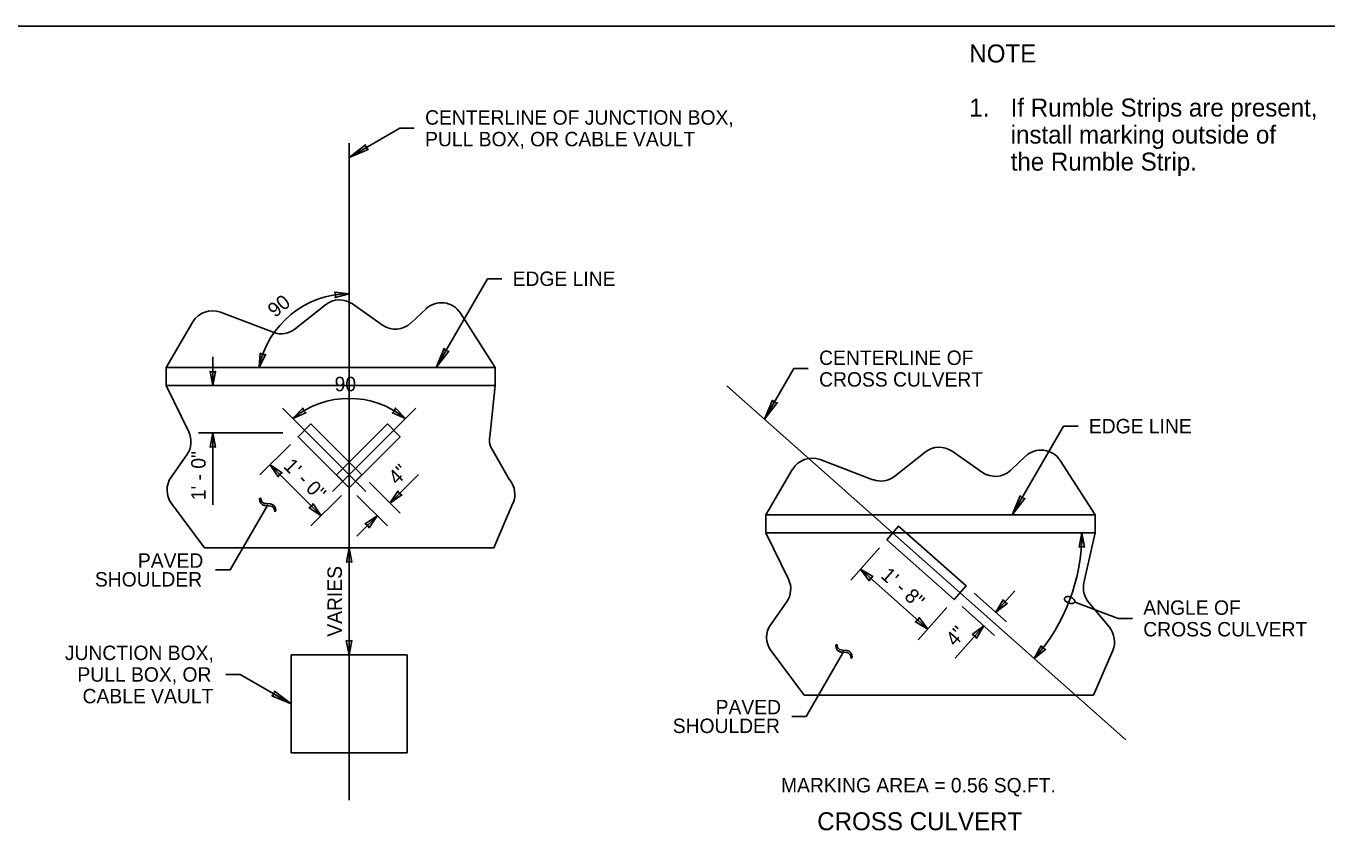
# Model space of a CAD drawing. Extents: x 99862 to 104211, y 98939 to 105076.
# Drawn here: x 101694 to 103137, y 101180 to 102076 of the extents above; entities that cross this region are included whole.
import ezdxf

# ---------------------------------------------------------------- set-up
doc = ezdxf.new("R2010")
doc.units = 0
for name, color, linetype in [('Level 1', 7, 'Continuous'), ('Level 15', 7, 'Continuous'), ('Level 17', 7, 'Continuous'), ('Level 20', 7, 'Continuous'), ('Level 5', 7, 'Continuous'), ('Level 50', 7, 'Continuous'), ('Level 8', 7, 'Continuous')]:
    doc.layers.add(name, color=color, linetype=linetype)

msp = doc.modelspace()

# ---------------------------------------------------------------- linework, layer by layer
at = {"layer": 'Level 1'}
msp.add_lwpolyline([(99862, 99999.5), (103151, 99999.5), (103151, 102075.5), (99862, 102075.5)], close=True, dxfattribs=at)
at = {"layer": 'Level 15'}
for p, q in [((102052.3, 101929.5), (102108.6, 101962)), ((102108.6, 101962), (102124.6, 101962)), ((102052.3, 101216.3), (102052.3, 101945.5)), ((102148.8, 101696.4), (102205.7, 101795)), ((102205.7, 101795), (102221.7, 101795)), ((101901.1, 101676.4), (101901.1, 101708.4)), ((102513.2, 101639), (102545.7, 101695.3)), ((102545.7, 101695.3), (102561.7, 101695.3)), ((102914.1, 101283.3), (102471.3, 101676.1)), ((102070.7, 101558.9), (101978.4, 101651.2)), ((102126.3, 101651.2), (102033.9, 101558.9)), ((102788, 101532.9), (102844.9, 101631.4)), ((102844.9, 101631.4), (102860.9, 101631.4)), ((101978.8, 101623.9), (101885.1, 101623.9)), ((101901.1, 101623.9), (101901.1, 101543.9)), ((101987.3, 101611.2), (101953.3, 101577.3)), ((101964.6, 101588.6), (102021.2, 101532)), ((102097.6, 101546.1), (102129.2, 101577.8)), ((102074.9, 101568.8), (102108.9, 101534.8)), ((101962, 101544.2), (101920.2, 101471.8)), ((101954.1, 101552), (101953, 101550.2)), ((101953, 101550.2), (101953.4, 101548.1)), ((101953.4, 101548.1), (101954, 101546.4)), ((101954, 101546.4), (101955, 101545.1)), ((101955.1, 101548.5), (101954.1, 101552)), ((101955, 101545.1), (101956.3, 101544.1)), ((101955.9, 101547.1), (101955.1, 101548.5)), ((101957, 101546.2), (101955.9, 101547.1)), ((101956.3, 101544.1), (101958.6, 101543.2)), ((101958.4, 101545.6), (101957, 101546.2)), ((101960.8, 101545.4), (101958.4, 101545.6)), ((101965.2, 101545.1), (101960.8, 101545.4)), ((101967.8, 101544.1), (101965.2, 101545.1)), ((101969.2, 101543.1), (101967.8, 101544.1)), ((102043.8, 101554.6), (102009.9, 101520.7)), ((102060.8, 101554.6), (102094.7, 101520.7)), ((101958.6, 101543.2), (101962.7, 101543)), ((101962.7, 101543), (101965.2, 101542.7)), ((101965.2, 101542.7), (101967, 101542.1)), ((101967, 101542.1), (101968.1, 101541.3)), ((101968.1, 101541.3), (101968.9, 101540.2)), ((101968.9, 101540.2), (101969.5, 101538.6)), ((101970.2, 101541.7), (101969.2, 101543.1)), ((101969.5, 101538.6), (101970, 101536.2)), ((101970, 101536.2), (101971.1, 101538)), ((101970.8, 101540), (101970.2, 101541.7)), ((101971.1, 101538), (101970.8, 101540)), ((102083.4, 101532), (102060.8, 101509.4)), ((102052.4, 101496.3), (102052.3, 101377.6)), ((102640.7, 101496.4), (102608.8, 101460.5)), ((101904.2, 101471.8), (101920.2, 101471.8)), ((102619.5, 101472.5), (102694.3, 101406.1)), ((102745.7, 101446), (102781.6, 101414.2)), ((102769.7, 101424.8), (102790.9, 101448.8)), ((102715.5, 101430.1), (102683.7, 101394.2)), ((102732.4, 101431.1), (102768.4, 101399.2)), ((102856.6, 101436.5), (102905.3, 101418)), ((102905.3, 101418), (102921.3, 101418)), ((102756.4, 101409.9), (102724.5, 101373.9)), ((102593.2, 101389.4), (102592.2, 101387.6)), ((102592.2, 101387.6), (102592.5, 101385.5)), ((102592.5, 101385.5), (102593.2, 101383.8)), ((102594.2, 101385.9), (102593.2, 101389.4)), ((102595.1, 101384.5), (102594.2, 101385.9)), ((102601.2, 101381.6), (102559.4, 101309.2)), ((102593.2, 101383.8), (102594.1, 101382.5)), ((102594.1, 101382.5), (102595.5, 101381.5)), ((102596.2, 101383.6), (102595.1, 101384.5)), ((102595.5, 101381.5), (102597.8, 101380.6)), ((102597.6, 101383), (102596.2, 101383.6)), ((102600, 101382.8), (102597.6, 101383)), ((102597.8, 101380.6), (102601.8, 101380.4)), ((102604.4, 101382.5), (102600, 101382.8)), ((102601.8, 101380.4), (102604.4, 101380.2)), ((102606.9, 101381.5), (102604.4, 101382.5)), ((102604.4, 101380.2), (102606.2, 101379.5)), ((102606.2, 101379.5), (102607.2, 101378.7)), ((102608.3, 101380.5), (102606.9, 101381.5)), ((102607.2, 101378.7), (102608, 101377.6)), ((102608, 101377.6), (102608.7, 101376)), ((102609.4, 101379.1), (102608.3, 101380.5)), ((102608.7, 101376), (102609.2, 101373.6)), ((102609.2, 101373.6), (102610.2, 101375.4)), ((102610, 101377.4), (102609.4, 101379.1)), ((102610.2, 101375.4), (102610, 101377.4)), ((101915.6, 101355.8), (101931.6, 101355.8)), ((101987.9, 101323.3), (101931.6, 101355.8)), ((102543.4, 101309.2), (102559.4, 101309.2))]:
    msp.add_line(p, q, dxfattribs=at)
for points in [[(102052.3, 101929.5), (102073.6, 101938.3), (102071.2, 101940.4), (102070.6, 101943.5)], [(102052.3, 101778.3), (102036.9, 101774.1), (102037.4, 101777.2), (102036.4, 101780.2)], [(102148.8, 101696.4), (102162.8, 101714.7), (102159.7, 101715.3), (102157.7, 101717.7)], [(101952.4, 101696.4), (101953.7, 101712.4), (101956.4, 101710.9), (101959.6, 101710.8)], [(101901.1, 101676.4), (101898, 101692.2), (101901.1, 101691.4), (101904.2, 101692.2)], [(102513.2, 101639), (102527.2, 101657.3), (102524, 101657.8), (102522, 101660.2)], [(101989.7, 101639.9), (102004.4, 101646.3), (102002, 101648.5), (102000.8, 101651.4)], [(102114.9, 101639.9), (102100.3, 101646.3), (102102.6, 101648.5), (102103.8, 101651.4)], [(101901.1, 101623.9), (101898, 101608.2), (101901.1, 101608.9), (101904.2, 101608.2)], [(101964.6, 101588.6), (101973.6, 101575.3), (101975.2, 101578), (101977.9, 101579.6)], [(102097.6, 101546.1), (102106.5, 101559.4), (102108.2, 101556.8), (102110.9, 101555.1)], [(102021.2, 101532), (102012.3, 101545.3), (102010.6, 101542.6), (102007.9, 101540.9)], [(102788, 101532.9), (102802, 101551.2), (102798.9, 101551.7), (102796.8, 101554.2)], [(102083.4, 101532), (102070.1, 101523.1), (102072.8, 101521.4), (102074.5, 101518.7)], [(102865.3, 101512.9), (102862, 101497.2), (102865.1, 101497.9), (102868.2, 101497.1)], [(102052.4, 101496.3), (102049.3, 101480.6), (102052.4, 101481.3), (102055.4, 101480.6)], [(102619.5, 101472.5), (102629.2, 101459.8), (102630.7, 101462.5), (102633.3, 101464.4)], [(102769.7, 101424.8), (102777.8, 101438.6), (102779.6, 101436), (102782.4, 101434.5)], [(102694.3, 101406.1), (102684.6, 101418.9), (102683.1, 101416.1), (102680.5, 101414.3)], [(102756.4, 101409.9), (102743.6, 101400.1), (102746.4, 101398.6), (102748.3, 101396)], [(102052.3, 101377.6), (102049.2, 101393.4), (102052.3, 101392.6), (102055.4, 101393.4)], [(102812.4, 101373.5), (102824.9, 101383.5), (102822.1, 101385), (102820.2, 101387.5)], [(101987.9, 101323.3), (101966.7, 101332.1), (101969.1, 101334.1), (101969.7, 101337.3)]]:
    msp.add_lwpolyline(points, close=True, dxfattribs=at)
for centre, radius, start, end in [((102052.3, 101676.4), 101.9, 90, 168.6784), ((102052.3, 101563.1), 99.1, 50.7921, 129.2072), ((102655.3, 101512.9), 210, 318.4255, 0)]:
    msp.add_arc(centre, radius, start, end, dxfattribs=at)
msp.add_ellipse((102851.6, 101438.4), major_axis=(5.61, -2.13), ratio=0.57735, dxfattribs=at)
at = {"layer": 'Level 17'}
for p, q in [((102214.5, 101696.4), (101849.2, 101696.4)), ((102214.5, 101676.4), (101849.2, 101676.4)), ((102514.5, 101532.9), (102879.8, 101532.9)), ((102655.3, 101512.9), (102514.5, 101512.9)), ((102879.8, 101512.9), (102670.4, 101512.9))]:
    msp.add_line(p, q, dxfattribs=at)
for points in [[(102052.3, 101591.4), (102094.7, 101633.8), (102108.9, 101619.7), (102052.3, 101563.1), (101995.7, 101619.7), (102009.9, 101633.8)], [(102648.7, 101505.4), (102723.5, 101439), (102736.7, 101454), (102661.9, 101520.4)]]:
    msp.add_lwpolyline(points, close=True, dxfattribs=at)
at = {"layer": 'Level 5'}
for p, q in [((102661.9, 101520.4), (102648.7, 101505.4)), ((102736.7, 101454), (102661.9, 101520.4)), ((102648.7, 101505.4), (102723.5, 101439.1)), ((102723.5, 101439), (102736.7, 101454)), ((102723.5, 101439.1), (102723.5, 101439))]:
    msp.add_line(p, q, dxfattribs=at)
for points in [[(101849.2, 101696.4), (102214.5, 101696.4), (102214.5, 101676.4), (101849.2, 101676.4)], [(102514.5, 101532.9), (102879.8, 101532.9), (102879.8, 101512.9), (102514.5, 101512.9)]]:
    msp.add_lwpolyline(points, close=True, dxfattribs=at)
for points in [[(102009.9, 101633.8), (101995.7, 101619.7), (102052.3, 101563.1), (102066.5, 101577.3), (102009.9, 101633.8)], [(102108.9, 101619.7), (102094.7, 101633.8), (102038.2, 101577.3), (102052.3, 101563.1), (102108.9, 101619.7)]]:
    msp.add_lwpolyline(points, dxfattribs=at)
at = {"layer": 'Level 50'}
for p, q in [((101992.5, 101739.3), (102026.2, 101766.1)), ((102056, 101767), (102089.5, 101743.6)), ((102121, 101746), (102137.6, 101761.6)), ((101909.5, 101757.8), (101968.1, 101735.6)), ((102212.2, 101603.8), (102230.4, 101571.8)), ((101854.8, 101574.8), (101872.4, 101599.6)), ((101891.9, 101496.4), (101855.2, 101545.4)), ((102234.1, 101545.9), (102212.8, 101496.4)), ((102212.8, 101496.4), (101891.9, 101496.4)), ((102878, 101332.9), (102557.1, 101332.9))]:
    msp.add_line(p, q, dxfattribs=at)
for points in [[(101874.4, 101625), (101849.2, 101676.4), (101849.2, 101696.4), (101879.1, 101747.2)], [(102175.8, 101756.9), (102214.5, 101696.4), (102214.5, 101676.4), (102208.4, 101619.6)], [(102657.8, 101575.8), (102691.4, 101602.5)], [(102721.3, 101603.5), (102754.8, 101580.1)], [(102574.8, 101594.3), (102633.3, 101572)], [(102786.3, 101582.4), (102802.8, 101598)], [(102841, 101593.3), (102879.8, 101532.9), (102879.8, 101512.9), (102867.4, 101457.5)], [(102539.7, 101461.5), (102514.5, 101512.9), (102514.5, 101532.9), (102544.3, 101583.6)], [(102520.1, 101411.3), (102537.6, 101436.1)], [(102872.6, 101436.1), (102895.7, 101408.2)], [(102557.1, 101332.9), (102520.5, 101381.9)], [(102899.4, 101382.4), (102878, 101332.9)]]:
    msp.add_lwpolyline(points, dxfattribs=at)
for centre, radius, start, end in [((102041.7, 101746.5), 25, 55.0975, 128.4802), ((102154.7, 101743.4), 25, 32.6491, 133.3153), ((101900.6, 101734.5), 25, 69.1602, 149.5358), ((102103.8, 101764.1), 25, 235.0975, 313.3153), ((101977, 101758.9), 25, 249.1602, 308.4802), ((101851.9, 101614.1), 25, 324.7824, 26.0823), ((102226.5, 101615.6), 18.6, 167.4249, 219.6743), ((102707, 101583), 25, 55.0975, 128.4802), ((102820, 101579.8), 25, 32.6491, 133.3153), ((102565.9, 101570.9), 25, 69.1602, 149.5358), ((101875.3, 101560.4), 25, 144.7824, 216.7745), ((102642.2, 101595.4), 25, 249.1602, 308.4802), ((102769.1, 101600.6), 25, 235.0975, 313.3153), ((102211.2, 101555.8), 25, 336.6664, 39.6743), ((102517.2, 101450.5), 25, 324.7824, 26.0823), ((102891.8, 101452.1), 25, 167.4249, 219.6743), ((102540.5, 101396.9), 25, 144.7824, 216.7745), ((102876.4, 101392.3), 25, 336.6664, 39.6743)]:
    msp.add_arc(centre, radius, start, end, dxfattribs=at)
at = {"layer": 'Level 8'}
for p, q in [((101891.9, 101496.4), (102212.8, 101496.4)), ((101987.9, 101268.9), (101987.9, 101377.6)), ((102116.7, 101377.6), (101987.9, 101377.6)), ((102116.7, 101377.6), (102116.7, 101268.9)), ((102557.1, 101332.9), (102878, 101332.9)), ((102116.7, 101268.9), (101987.9, 101268.9))]:
    msp.add_line(p, q, dxfattribs=at)

# ---------------------------------------------------------------- texts
at = {"layer": 'Level 20'}
for s, height, p in [('NOTE', 20, (102740.3, 102035)), ('1.', 20, (102740.3, 101975)), ('If Rumble Strips are present,', 20, (102786.2, 101975)), ('CENTERLINE OF JUNCTION BOX, ', 16, (102136.6, 101966)), ('install marking outside of', 20, (102786.2, 101945)), ('PULL BOX, OR CABLE VAULT', 16, (102136.6, 101942)), ('the Rumble Strip.', 20, (102786.2, 101915)), ('EDGE LINE', 16, (102233.7, 101787)), ('CENTERLINE OF', 16, (102573.7, 101699.3)), ('CROSS CULVERT', 16, (102573.7, 101675.3)), ('90', 16, (102036.2, 101670.2)), ('EDGE LINE', 16, (102872.9, 101623.4)), ('PAVED', 16, (101818, 101474.2)), ('SHOULDER', 16, (101770.3, 101453.4)), ('ANGLE OF', 16, (102933.3, 101422)), ('CROSS CULVERT', 16, (102933.3, 101398)), ('JUNCTION BOX,', 16, (101737, 101371.8)), ('PULL BOX, OR', 16, (101750.9, 101347.8)), ('CABLE VAULT', 16, (101756.6, 101323.8)), ('PAVED', 16, (102458.9, 101311.6)), ('SHOULDER', 16, (102411.3, 101290.8)), ('MARKING AREA = 0.56 SQ.FT.', 16, (102531.4, 101224.9)), ('CROSS CULVERT', 20, (102571.6, 101182.9))]:
    msp.add_text(s, height=height, dxfattribs=at).set_placement(p)
for s, rotation, p in [('90', 39.3392, (101970.2, 101751.2)), ('1\' - 0"', 90, (101893.1, 101549.2)), ('1\' - 0"', 315, (101978.5, 101586)), ('4"', 45, (102105.5, 101565.4)), ('VARIES', 90, (102044.3, 101397.7)), ('1\' - 8"', 318.4248, (102641, 101464.1)), ('4"', 48.4248, (102724.6, 101386))]:
    msp.add_text(s, height=16, rotation=rotation, dxfattribs=at).set_placement(p)

doc.saveas('drawing.dxf')
